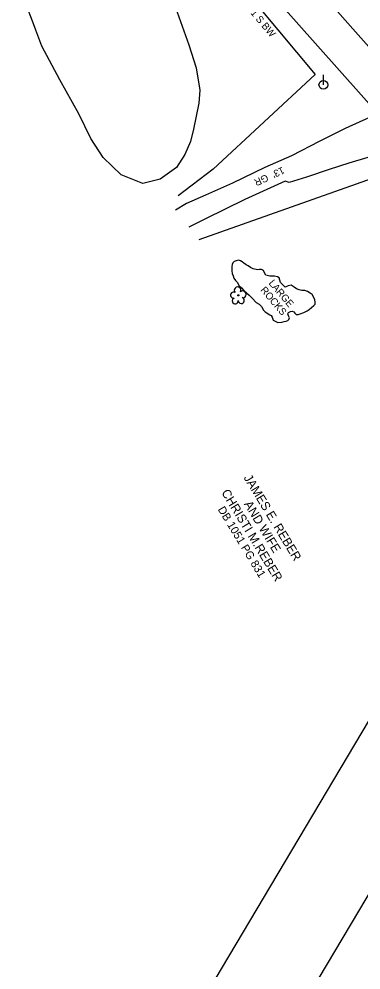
# Model space of a CAD drawing. Extents: x 1498375 to 1499839, y 700490 to 702854.
# Drawn here: x 1498425 to 1498617, y 702024 to 702558 of the extents above; entities that cross this region are included whole.
import ezdxf

# ---------------------------------------------------------------- set-up
doc = ezdxf.new("R2010")
doc.units = 0
for name, color, linetype in [('Exist Other Culture Area Outline', 7, 'Continuous'), ('Exist Other Culture Area Outline Text', 7, 'Continuous'), ('Exist Other Culture Fence Line', 7, 'Continuous'), ('Exist Other Culture Fence Line Text', 7, 'Continuous'), ('Exist Property Deed Book Text', 7, 'Continuous'), ('Exist Property Line', 7, 'Continuous'), ('Exist Property Owner Text', 7, 'Continuous'), ('Exist Right of Way Easement Line', 7, 'Continuous'), ('Exist Right of Way Line', 7, 'Continuous'), ('Exist Roads EOP', 7, 'Continuous'), ('Exist Roads Soil', 7, 'Continuous'), ('Exist Roads Soil Text', 7, 'Continuous'), ('Exist Utilities Power Pole CELL', 7, 'Continuous'), ('Exist Vegetation Tree CELL', 7, 'Continuous'), ('Exist Vegetation Woods Line', 7, 'Continuous')]:
    doc.layers.add(name, color=color, linetype=linetype)

# ---------------------------------------------------------------- blocks, each defined once
blk = doc.blocks.new('EXIST UTILITIES POWER POLE')
at = {"layer": 'Exist Utilities Power Pole CELL'}
for q in [(0, 0.1125), (0, 0)]:
    blk.add_line((0, 0), q, dxfattribs=at)
blk.add_circle((0, 0), 0.049, dxfattribs=at)

msp = doc.modelspace()

# ---------------------------------------------------------------- linework, layer by layer
at = {"layer": 'Exist Other Culture Area Outline'}
msp.add_lwpolyline([(1498557.8, 702399.12), (1498559.4, 702398.1), (1498560.69, 702396.86), (1498561.92, 702394.82), (1498562.75, 702393.83), (1498563.66, 702393.28), (1498564.55, 702392.8), (1498565.4, 702392.14), (1498566.18, 702391.77), (1498566.71, 702390.81), (1498567.38, 702389.1), (1498569.94, 702387.79), (1498572.15, 702388.09), (1498573.51, 702388.41), (1498574.67, 702388.58), (1498575.57, 702388.92), (1498576.19, 702389.6), (1498576.46, 702390.49), (1498576, 702391.7), (1498575.64, 702392.64), (1498576.01, 702393.53), (1498577.14, 702394.01), (1498578.04, 702394.15), (1498578.94, 702393.86), (1498579.55, 702393.07), (1498580.31, 702392.29), (1498581.45, 702392.38), (1498582.45, 702392.76), (1498584.47, 702393.57), (1498586.35, 702394.4), (1498587.54, 702395.16), (1498588.81, 702396.28), (1498590.07, 702397.43), (1498590.85, 702398.1), (1498590.99, 702399.25), (1498590.7, 702400.58), (1498590.01, 702402.36), (1498589.24, 702403.52), (1498588.02, 702404.33), (1498586.54, 702405.32), (1498585.16, 702405.82), (1498583.48, 702405.84), (1498581.92, 702406.14), (1498580.44, 702406.82), (1498579.09, 702407.78), (1498577.39, 702408.79), (1498575.65, 702408.4), (1498574.06, 702407.78), (1498571.47, 702410.41), (1498571.12, 702411.71), (1498570.67, 702412.88), (1498569.74, 702413.49), (1498568.14, 702413.81), (1498565.35, 702413.87), (1498563.11, 702414.44), (1498562.53, 702415.84), (1498561.91, 702417.12), (1498560.77, 702417.56), (1498559.54, 702417.64), (1498558.57, 702417.54), (1498556.16, 702418), (1498554.64, 702418.82), (1498553.19, 702419.71), (1498552.17, 702420.35), (1498550.9, 702421.2), (1498549.93, 702421.91), (1498548.89, 702422.54), (1498547.79, 702422.82), (1498546.6, 702422.59), (1498545.4, 702422.09), (1498544.62, 702421.48), (1498544.26, 702420.41), (1498544.14, 702419.37), (1498544.11, 702418.11), (1498544.15, 702416.83), (1498544.29, 702415.39), (1498544.78, 702414.13), (1498545.28, 702412.83), (1498546.15, 702411.43), (1498547.22, 702410.25), (1498548.11, 702408.74), (1498549.51, 702407.35), (1498550.88, 702405.86), (1498552.34, 702404.52), (1498553.77, 702403.23), (1498555.6, 702401.55), (1498557.8, 702399.12)], dxfattribs=at)
at = {"layer": 'Exist Other Culture Fence Line'}
for points in [[(1498435.06, 702716.62), (1498458.98, 702689.21), (1498480.24, 702665.6), (1498439.57, 702634.74), (1498453.85, 702607.62), (1498528.88, 702601.21), (1498559.48, 702564.89), (1498590.87, 702527.24), (1498533.64, 702474.05)], [(1498525.72, 702434.51), (1498653.91, 702479.77)], [(1498533.64, 702474.05), (1498513.92, 702459)]]:
    msp.add_lwpolyline(points, dxfattribs=at)
at = {"layer": 'Exist Property Line'}
msp.add_line((1498467.5, 701808.33), (1498779.43, 702332.92), dxfattribs=at)
at = {"layer": 'Exist Right of Way Easement Line'}
msp.add_line((1498744.54, 702372.08), (1498424.52, 701833.88), dxfattribs=at)
at = {"layer": 'Exist Right of Way Line'}
msp.add_line((1498439.6, 702714.95), (1498774.58, 702338.31), dxfattribs=at)
at = {"layer": 'Exist Roads EOP'}
msp.add_lwpolyline([(1498769.18, 702377.27), (1498736.01, 702414.78), (1498705.53, 702448.2), (1498674.18, 702483.19), (1498644.92, 702516.03), (1498612.09, 702552.96), (1498580.72, 702588.4), (1498548.96, 702624.17), (1498517.86, 702658.21), (1498486.49, 702694.05), (1498455.23, 702728.77)], dxfattribs=at)
at = {"layer": 'Exist Roads Soil'}
for points in [[(1498639.14, 702522.53), (1498639.89, 702520.6), (1498640.49, 702517.74), (1498639.67, 702515.59), (1498638.04, 702513.34), (1498634.85, 702511.32), (1498627.99, 702507.1), (1498621.38, 702503.1), (1498607.7, 702496.8), (1498593.56, 702489.77), (1498577.61, 702481.55), (1498562.67, 702474.99), (1498544.44, 702466.1), (1498529.29, 702459.43), (1498518.55, 702454.65), (1498512.51, 702451.01)], [(1498662.32, 702496.5), (1498660.43, 702496.42), (1498656.69, 702496.02), (1498652.29, 702494.69), (1498647.66, 702493.08), (1498641.2, 702490.5), (1498632.08, 702485.82), (1498620.45, 702480.67), (1498609.9, 702477.38), (1498598.71, 702473.87), (1498586.03, 702469.6), (1498576.36, 702466.54), (1498574.01, 702467.37), (1498551.39, 702456.9), (1498529.22, 702446.2), (1498519.91, 702441.38)]]:
    msp.add_lwpolyline(points, dxfattribs=at)
at = {"layer": 'Exist Vegetation Tree CELL'}
msp.add_line((1498547.7, 702403.09), (1498547.7, 702403.09), dxfattribs=at)
msp.add_circle((1498547.7, 702403.09), 0.326, dxfattribs=at)
for centre, radius, start, end in [((1498547.32, 702405.96), 1.86, 330.1651, 219.7134), ((1498545.1, 702403.24), 1.73, 62.6636, 279.3457), ((1498549.38, 702400.19), 1.7, 181.2822, 74.56), ((1498550.25, 702403.68), 1.9, 257.1011, 134.1999), ((1498546, 702399.97), 1.69, 111.5671, 6.231)]:
    msp.add_arc(centre, radius, start, end, dxfattribs=at)
at = {"layer": 'Exist Vegetation Woods Line'}
msp.add_lwpolyline([(1498510.63, 702570.35), (1498519.87, 702543.88), (1498524.05, 702530.95), (1498526.12, 702518.47), (1498525.47, 702511.18), (1498522.63, 702496.57), (1498520.78, 702489.52), (1498517.71, 702482.34), (1498513.04, 702474.91), (1498503.76, 702468.33), (1498494.09, 702465.96), (1498481.82, 702470.75), (1498471.74, 702480.55), (1498464.91, 702491.27), (1498458.12, 702505.13), (1498447.47, 702524.18), (1498437.42, 702543.23), (1498434, 702552.14), (1498432.08, 702557.13), (1498428.86, 702565.44)], dxfattribs=at)

# ---------------------------------------------------------------- block references
at = {"layer": 'Exist Utilities Power Pole CELL', "xscale": 50, "yscale": 50}
msp.add_blockref('EXIST UTILITIES POWER POLE', (1498595.51, 702521.43), dxfattribs=at)

# ---------------------------------------------------------------- texts
at = {"layer": 'Exist Other Culture Area Outline Text'}
for s, p in [('ROCKS', (1498559.92, 702405.98)), ('LARGE', (1498564.51, 702409.84))]:
    msp.add_text(s, height=4, rotation=310.2308, dxfattribs=at).set_placement(p)
at = {"layer": 'Exist Other Culture Fence Line Text'}
msp.add_text('48" WW W/ 1 S BW', height=4, rotation=310.1114, dxfattribs=at).set_placement((1498535.71, 702583.8))
at = {"layer": 'Exist Property Deed Book Text'}
msp.add_text('DB 1051 PG 831', height=4.5, rotation=301.2023, dxfattribs=at).set_placement((1498536.03, 702282.86))
at = {"layer": 'Exist Property Owner Text'}
for s, p in [('JAMES E. REBER', (1498550.53, 702300.65)), ('CHRISTI M.REBER', (1498538.04, 702292.31)), ('AND WIFE', (1498550.73, 702285.84))]:
    msp.add_text(s, height=5, rotation=301.2023, dxfattribs=at).set_placement(p)
at = {"layer": 'Exist Roads Soil Text'}
msp.add_text("13'  GR", height=4, rotation=204.8361, dxfattribs=at).set_placement((1498572.49, 702475.49))

doc.saveas('drawing.dxf')
